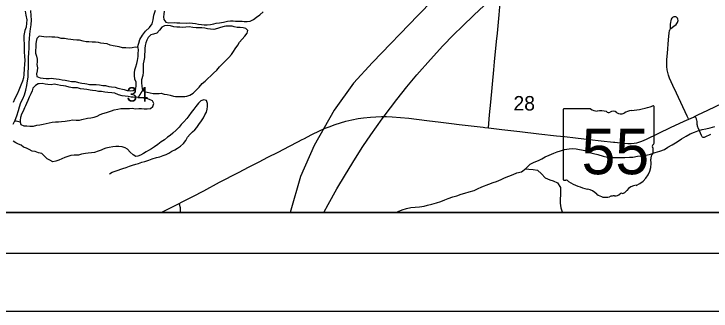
# Model space of a CAD drawing. Extents: x 0 to 1067, y 0 to 440.
# Drawn here: x 227.4 to 348.6, y 0 to 51.6 of the extents above; entities that cross this region are included whole.
import ezdxf

# ---------------------------------------------------------------- set-up
doc = ezdxf.new("R2010")
doc.units = 0
for name, color, linetype in [('GM_X_City_Street', 7, 'Continuous'), ('GM_X_County_Road', 7, 'Continuous'), ('GM_X_Major_River', 7, 'Continuous'), ('GM_X_Minor_Lake', 7, 'Continuous'), ('GM_X_Minor_River', 7, 'Continuous'), ('GM_X_Rail_Line', 7, 'Continuous'), ('GM_X_Section_Text', 7, 'Continuous'), ('GM_X_State_Location', 7, 'Continuous'), ('GM_X_State_Route', 7, 'Continuous'), ('GM_X_State_Shield', 7, 'Continuous'), ('GM_X_Township_Road', 7, 'Continuous'), ('SH_Border', 7, 'Continuous'), ('SH_Cut_Line', 7, 'Continuous'), ('SH_Text', 7, 'Continuous')]:
    doc.layers.add(name, color=color, linetype=linetype)

msp = doc.modelspace()

# ---------------------------------------------------------------- linework, layer by layer
at = {"layer": 'GM_X_City_Street'}
for points in [[(344.76, 33.32), (344.72, 33.41), (344.5, 33.86), (342.65, 37.82), (341.99, 39.2), (341.42, 40.46), (341.23, 40.95), (341.1, 41.42), (341.01, 41.9), (340.94, 42.46), (340.92, 43.03), (340.94, 43.66), (341.04, 44.78), (341.26, 47.12), (341.37, 48.32), (341.41, 48.64), (341.46, 48.84), (341.52, 48.98), (341.64, 49.09), (342.18, 49.48), (342.55, 49.77), (342.7, 49.94), (342.79, 50.1), (342.85, 50.26), (342.89, 50.48), (342.88, 50.68), (342.83, 50.85), (342.76, 50.95), (342.65, 51.03), (342.5, 51.08), (342.35, 51.1), (342.18, 51.09), (342.05, 51.05), (341.94, 50.98), (341.82, 50.85), (341.71, 50.67), (341.62, 50.43), (341.57, 50.19), (341.52, 49.75), (341.51, 49.41), (341.5, 49.02)], [(348.56, 30.65), (347.56, 30.18), (347.46, 30.15), (347.35, 30.14), (347.25, 30.16), (347.15, 30.2), (347.07, 30.28), (347.01, 30.36), (346.95, 30.47), (346.37, 31.81), (346.32, 31.95), (346.29, 32.1), (346.26, 32.24), (346.24, 32.39), (346.22, 32.6), (346.2, 32.91), (346.17, 33.13), (346.13, 33.26), (346.09, 33.38), (346.04, 33.5), (345.89, 33.85)]]:
    msp.add_lwpolyline(points, dxfattribs=at)
at = {"layer": 'GM_X_County_Road'}
msp.add_lwpolyline([(309.92, 31.81), (310.12, 34.06), (310.32, 36.28), (310.87, 41.91), (311, 43.28), (311.35, 46.83), (311.48, 48.24), (311.79, 51.47), (311.99, 53.51), (312.23, 55.99), (312.6, 59.78), (312.83, 62.08)], dxfattribs=at)
at = {"layer": 'GM_X_Major_River'}
for points in [[(227.27, 32.46), (227.63, 33.16), (227.94, 33.93), (228.23, 34.84), (228.4, 35.45), (228.62, 36.23), (228.97, 36.88), (229.24, 37.56), (229.48, 38.36), (229.66, 39.18), (229.76, 39.97), (229.87, 40.63), (229.9, 41.45), (229.94, 42.32), (229.97, 44.05), (230.01, 44.78), (230.05, 45.7), (230.04, 46.63), (230.1, 47.25), (230.18, 48.09), (230.29, 49.02), (230.4, 49.71), (230.44, 50.55), (230.4, 51.28), (230.33, 52.2)], [(229.34, 52.08), (229.49, 51.39), (229.64, 50.59), (229.62, 49.97), (229.54, 49.33), (229.33, 48.72), (229.13, 47.84), (229.14, 47.13), (229.17, 46.4), (229.2, 45.69), (229.19, 44.96), (229.25, 44.25), (229.28, 43.52), (229.24, 42.88), (229.21, 42.08), (229.14, 41.1), (229.06, 40.51), (228.87, 39.9), (228.63, 39.24), (228.27, 38.36), (227.96, 37.68), (227.58, 36.91), (227.29, 36.23)]]:
    msp.add_lwpolyline(points, dxfattribs=at)
at = {"layer": 'GM_X_Minor_Lake'}
for points in [[(253.55, 52.09), (253.47, 51.55), (253.44, 51.07), (253.5, 50.61), (253.84, 50.15), (254.32, 50.08), (255.37, 50.11), (255.75, 50.08), (256.28, 50.03), (257.5, 50.01), (258.01, 50.03), (258.48, 50.02), (258.96, 49.95), (259.48, 49.83), (260.03, 49.75), (260.51, 49.72), (261.01, 49.72), (261.62, 49.78), (262.17, 49.91), (262.58, 49.99), (263.15, 50.08), (263.84, 50.16), (264.52, 50.33), (265.07, 50.42), (265.55, 50.39), (265.94, 50.36), (266.55, 50.37), (267.1, 50.32), (267.44, 50.29), (267.96, 50.29), (268.47, 50.37), (269.08, 50.66), (269.59, 51.04), (270.17, 51.44), (270.74, 51.94)], [(264.25, 43.53), (264.8, 44.02), (265.22, 44.56), (265.59, 45.06), (265.87, 45.55), (266.33, 46.16), (266.64, 46.68), (267.12, 47.2), (267.56, 47.74), (267.96, 48.26), (268.1, 48.74), (267.76, 49.08), (267.29, 49.2), (266.76, 49.25), (266.2, 49.26), (265.72, 49.38), (265.33, 49.46), (264.28, 49.47), (263.94, 49.43), (263.35, 49.23), (262.8, 49.06), (262.18, 48.88), (261.59, 48.94), (261.07, 49.01), (260.59, 49.15), (260.09, 49.18), (259.57, 49.21), (259.07, 49.2), (258.5, 49.25), (257.86, 49.35), (257.29, 49.29), (256.79, 49.27), (256.24, 49.33), (255.74, 49.33), (255.24, 49.38), (254.65, 49.51), (254.15, 49.58), (253.6, 49.56), (253.12, 49.28), (252.7, 48.78), (252.24, 48.28), (251.69, 48.11), (251.19, 47.96), (250.75, 47.53), (250.52, 47.05), (250.35, 46.6), (250.23, 46.12), (250.2, 45.62), (250.19, 45.08), (250.14, 44.58), (250.09, 44.01), (249.99, 43.48), (249.91, 42.94), (249.86, 42.44), (249.88, 41.91), (249.89, 41.46), (249.84, 40.93), (249.62, 40.14)], [(231.8, 47.73), (231.41, 47.31), (231.27, 46.83), (231.22, 46.38), (231.21, 45.81), (231.18, 45.26), (231.17, 44.76), (231.32, 44.26), (231.43, 43.73), (231.47, 43.27), (231.39, 42.8), (231.48, 42.25), (231.47, 41.72), (231.35, 41.22), (231.37, 40.72), (231.98, 40.49), (232.5, 40.46), (233.02, 40.4), (233.55, 40.4), (233.89, 40.42), (234.28, 40.36), (234.75, 40.34), (235.3, 40.26), (235.8, 40.16), (236.3, 40.09), (236.87, 39.97), (237.41, 39.87), (238.05, 39.84), (238.64, 39.71), (239.21, 39.59), (239.71, 39.5), (240.07, 39.44), (240.55, 39.35), (241.16, 39.32), (241.71, 39.33), (242.26, 39.3), (242.85, 39.2), (243.32, 39.15), (243.94, 39.01), (244.37, 38.95), (245.01, 38.86), (245.48, 38.71), (246.57, 38.47), (247.09, 38.33), (247.62, 38.25), (248.14, 38.31), (248.44, 38.52)], [(248.44, 38.52), (248.6, 38.63), (248.68, 39.13), (248.66, 39.74), (248.46, 40.29), (248.36, 40.88), (248.37, 41.39), (248.42, 41.89), (248.63, 42.43), (248.78, 43), (248.87, 43.52), (249.02, 44.18), (249.03, 44.75), (249.06, 45.3), (249.02, 45.77), (248.5, 45.83), (247.99, 45.74), (247.47, 45.68), (246.85, 45.69), (246.31, 45.72), (245.72, 45.89), (244.67, 46.04), (244.13, 46.18), (243.61, 46.39), (243.06, 46.47), (242.54, 46.54), (242.13, 46.64), (241.58, 46.72), (240.99, 46.72), (240.45, 46.75), (239.99, 46.76), (239.47, 46.86), (238.81, 47.03), (238.33, 47.06), (237.69, 47.11), (237.33, 47.18), (236.79, 47.24), (236.22, 47.31), (235.63, 47.34), (235.08, 47.49), (234.53, 47.54), (233.97, 47.59), (233.56, 47.6), (233.01, 47.56), (231.8, 47.73)], [(249.62, 40.14), (249.59, 39.62), (249.65, 39.07), (249.72, 38.57), (250.07, 38.15), (250.55, 38.01), (251.12, 37.89), (251.64, 37.81), (252.19, 37.78), (252.67, 37.8), (253.01, 37.82), (253.53, 37.69), (254.03, 37.6), (254.58, 37.48), (255.17, 37.31), (255.51, 37.26), (256.05, 37.25), (256.64, 37.27), (257.1, 37.28), (257.47, 37.32), (257.99, 37.52), (258.57, 37.86), (259.1, 38.35), (259.61, 38.91), (260.14, 39.52), (260.65, 39.95), (261.13, 40.37), (261.64, 40.87), (262.12, 41.3), (262.68, 41.84), (263.16, 42.4), (263.69, 42.94), (264.25, 43.53)], [(231.62, 39.49), (231.14, 39.18), (230.7, 38.73), (230.56, 38.27), (230.32, 37.73), (230.06, 37.16), (229.8, 36.57), (229.59, 36.03), (229.4, 35.64), (229.24, 35.28), (229, 34.72), (228.72, 34.2), (228.56, 33.63), (228.48, 33.17), (228.5, 32.83), (228.61, 32.37), (229.13, 32.14), (229.67, 32.15), (230.2, 32.08), (230.81, 32.12), (231.38, 32.27), (231.89, 32.35), (232.48, 32.46), (233.03, 32.59), (233.53, 32.67), (234.06, 32.78), (234.63, 32.86), (235.13, 32.88), (235.68, 32.92), (236.29, 32.98), (236.68, 33.02), (237.07, 33.08), (237.59, 33.19), (238.25, 33.16), (238.82, 33.17), (239.19, 33.26), (240.19, 33.47), (240.76, 33.58), (241.36, 33.69), (241.91, 33.84), (242.39, 34.13), (242.89, 34.3), (243.53, 34.48), (244.01, 34.63), (244.36, 34.76), (244.86, 34.96), (245.45, 35.07), (245.98, 35.15), (246.43, 35.15), (247.03, 35.18), (247.53, 35.2), (247.98, 35.22), (248.53, 35.14), (249.15, 35.16)], [(249.15, 35.16), (249.58, 35.15), (250.08, 35.1), (250.6, 35.11), (251.15, 35.15), (251.54, 35.53), (251.75, 36.03), (251.49, 36.49), (250.99, 36.73), (250.51, 36.89), (250.15, 36.94), (249.63, 37.02), (249.13, 37.11), (248.12, 37.13), (247.78, 37.16), (247.26, 37.28), (246.76, 37.31), (246.21, 37.36), (245.58, 37.57), (244.95, 37.83), (244.42, 37.88), (243.74, 37.94), (243.19, 38.04), (242.65, 38.11), (242.1, 38.12), (241.63, 38.22), (241.06, 38.29), (240.67, 38.37), (240.1, 38.46), (239.56, 38.52), (238.99, 38.62), (238.49, 38.74), (237.97, 38.79), (237.58, 38.77), (237.03, 38.89), (236.42, 39.08), (236.04, 39.13), (235.51, 39.16), (234.97, 39.26), (234.4, 39.38), (233.9, 39.3), (233.33, 39.33), (232.83, 39.4), (232.31, 39.53), (231.78, 39.49), (231.62, 39.49)], [(257.29, 29.6), (257.59, 30.17), (258.06, 30.73), (258.47, 31.11), (258.84, 31.47), (259.24, 31.88), (259.58, 32.4), (260.03, 33.05), (260.4, 33.53), (260.63, 34.07), (260.87, 34.54), (261.03, 35.04), (261.09, 35.54), (261.07, 36.05), (260.92, 36.55), (260.42, 36.67), (259.91, 36.49), (259.52, 36.09), (259.06, 35.55), (258.69, 35.07), (258.25, 34.47), (257.81, 33.92), (257.48, 33.45), (256.97, 32.86), (256.51, 32.37), (256.12, 31.94), (255.63, 31.42), (255.05, 30.91), (254.55, 30.5), (254.11, 30.19), (253.58, 29.76), (253.03, 29.36), (252.45, 28.94), (251.88, 28.53), (251.33, 28.18), (250.8, 27.89), (250.38, 27.66), (249.92, 27.35), (249.44, 27.06), (248.96, 26.89), (248.62, 26.82), (248.12, 27.12), (247.63, 27.61), (247.18, 28.09), (246.73, 28.37), (246.21, 28.54), (245.66, 28.55), (245.11, 28.6), (244.59, 28.54), (243.97, 28.41), (243.4, 28.3), (242.92, 28.11), (242.55, 27.95), (242.03, 27.78), (241.39, 27.56), (240.88, 27.45), (240.34, 27.41), (239.86, 27.37), (239.13, 27.22), (238.62, 27.09), (237.89, 27.06), (237.32, 27.04), (236.8, 26.84), (236.25, 26.67), (235.74, 26.45), (235.2, 26.23), (234.69, 26.03), (234.17, 25.94), (233.67, 26.18), (233.17, 26.43), (232.74, 26.9), (232.27, 27.38), (231.7, 27.46), (231.09, 27.69), (230.55, 27.77), (230.05, 28.07), (229.57, 28.26), (229.05, 28.49), (228.67, 28.8), (228.22, 29.01), (227.72, 29.24), (227.27, 29.48)], [(244.02, 23.81), (244.48, 24.1), (245.03, 24.29), (245.51, 24.47), (246.01, 24.62), (246.36, 24.76), (246.91, 24.95), (247.53, 25.17), (248.03, 25.35), (248.6, 25.52), (249.06, 25.63), (249.63, 25.85), (250.18, 25.98), (250.84, 26.2), (251.42, 26.42), (252.22, 26.64), (252.79, 26.79), (253.34, 26.99), (253.91, 27.19), (254.34, 27.41), (254.87, 27.76), (255.38, 28.01), (255.86, 28.28), (256.37, 28.63), (256.87, 29.08), (257.29, 29.6)]]:
    msp.add_lwpolyline(points, dxfattribs=at)
at = {"layer": 'GM_X_Minor_River'}
for points in [[(248.92, 45.78), (249.14, 46.55), (249.33, 47.16), (249.75, 47.91), (250.29, 48.61), (251, 49.26), (251.47, 49.87), (251.61, 50.59), (251.74, 51.41), (252.05, 52.23)], [(227.55, 33.01), (227.82, 33.05), (228.5, 32.85)], [(309.98, 22.06), (310.74, 22.32), (311.31, 22.51), (312.11, 22.86), (312.73, 23.13), (313.47, 23.41), (314.2, 23.74), (314.84, 23.98), (315.67, 24.19), (316.45, 24.77), (317.17, 25.51), (317.88, 25.86), (318.62, 26.17), (319.19, 26.43), (319.77, 26.79), (320.48, 27.05), (321.3, 27.42), (321.88, 27.64), (322.45, 27.84), (323.18, 28.05), (323.98, 28.2), (324.58, 28.24), (325.17, 28.16), (326.67, 27.9), (327.5, 27.55), (328.18, 27.35), (328.95, 27.16), (329.86, 26.89), (330.61, 26.74), (331.52, 26.64), (332.25, 26.65), (332.84, 26.66), (333.66, 26.67), (334.43, 26.72), (335.05, 26.74), (335.83, 26.88), (336.62, 26.98), (337.35, 27.08), (338.13, 27.25), (338.89, 27.54), (339.73, 27.75), (340.54, 28.08), (341.14, 28.46), (341.87, 28.85), (342.75, 29.39), (343.51, 29.9), (344.29, 30.36), (344.98, 30.76), (345.74, 31.07), (346.31, 31.28), (347.09, 31.54), (347.73, 31.65), (348.46, 31.8), (349.31, 32.03)], [(316.34, 24.69), (316.95, 24.65), (317.68, 24.59), (318.45, 24.49), (319.17, 23.84), (319.77, 23.14), (320.59, 22.79), (321.17, 22.64), (321.94, 22.29), (322.43, 21.48), (322.46, 20.82), (322.43, 20.09), (322.4, 19.52), (322.4, 18.72), (322.5, 17.95), (322.72, 17.24), (322.78, 17.11)], [(293.91, 17.11), (294.23, 17.26), (294.94, 17.59), (295.7, 17.79), (296.45, 17.96), (297.18, 18.03), (297.91, 18.09), (298.76, 18.21), (299.35, 18.36), (300.1, 18.55), (300.88, 18.79), (301.64, 19.03), (302.35, 19.34), (302.95, 19.53), (303.75, 19.81), (304.41, 20.03), (305.21, 20.31), (305.83, 20.49), (306.57, 20.72), (307.44, 20.96), (308.03, 21.22), (308.79, 21.58), (309.98, 22.06)]]:
    msp.add_lwpolyline(points, dxfattribs=at)
at = {"layer": 'GM_X_Rail_Line'}
for points in [[(330.43, 84.61), (324.5, 78.63), (310.59, 64.57), (297.7, 51.37), (289.79, 43.17), (286.47, 39.55), (283.11, 34.86), (279.61, 28.76), (277.25, 23.39), (275.45, 17.11)], [(281.31, 17.11), (282.06, 18.52), (283.58, 21.24), (285.05, 23.74), (286.82, 26.55), (288.11, 28.57), (289.49, 30.6), (291.47, 33.38), (292.88, 35.27), (294.01, 36.75), (295.75, 38.93), (297.48, 41.04), (299.85, 43.69), (302.01, 46.04), (303.85, 47.95), (305.4, 49.48), (307.36, 51.37), (309.16, 53.05)]]:
    msp.add_lwpolyline(points, dxfattribs=at)
at = {"layer": 'GM_X_State_Route'}
for points in [[(331.89, 29.32), (333.27, 29.17), (334.15, 29.1), (334.75, 29.1), (335.27, 29.14), (335.72, 29.22), (336.09, 29.31), (336.61, 29.51), (337.4, 29.86), (341.58, 31.85), (343.95, 32.95), (344.76, 33.32), (345.56, 33.7), (345.89, 33.85), (346.35, 34.07), (348.08, 34.9), (350.64, 36.11), (351.62, 36.57)], [(280.69, 31.37), (281.43, 31.7), (281.68, 31.81), (282.2, 32.02), (283.28, 32.42), (284.17, 32.71), (285.14, 32.97), (286.15, 33.22), (287.25, 33.43), (288.21, 33.57), (289.39, 33.69), (290.34, 33.75), (291.32, 33.78)], [(291.32, 33.78), (291.54, 33.78), (292.2, 33.78)], [(292.2, 33.78), (293.21, 33.74), (294.61, 33.64), (296.09, 33.47), (299.23, 33.07), (301.64, 32.79), (303.49, 32.57)], [(303.49, 32.57), (304.86, 32.42), (309, 31.92), (309.31, 31.88)], [(309.31, 31.88), (309.92, 31.81), (312.26, 31.54), (315.37, 31.17), (318.7, 30.8), (321.75, 30.45)], [(277.8, 29.92), (279.23, 30.65), (280.52, 31.3), (280.69, 31.37)], [(321.75, 30.45), (323.18, 30.29), (325.07, 30.07), (327.48, 29.81), (329.53, 29.57), (331.65, 29.35), (331.89, 29.32)], [(253.01, 17.11), (254.51, 17.87), (256.15, 18.68), (256.67, 18.95), (258.52, 19.91), (260.41, 20.9), (263.17, 22.36), (266.46, 24.04), (268.34, 25.03), (270.03, 25.9), (271.58, 26.71), (273.34, 27.6), (275.35, 28.66), (276.79, 29.4)], [(276.79, 29.4), (277.54, 29.79), (277.8, 29.92)]]:
    msp.add_lwpolyline(points, dxfattribs=at)
at = {"layer": 'GM_X_State_Shield'}
for p, q in [((338.73, 29.14), (338.73, 35.42)), ((322.91, 34.92), (322.91, 22.91)), ((327.7, 35.13), (323.06, 35.13)), ((338.73, 29.14), (338.73, 29.14))]:
    msp.add_line(p, q, dxfattribs=at)
for centre, radius, start, end in [((333.09, 51.5), 16.78, 275.8445, 288.9065), ((338.55, 35.45), 0.176, 351.8621, 97.738), ((323.09, 34.94), 0.183, 98.1301, 188.1301), ((328.8, 36.52), 1.78, 231.6195, 271.1119), ((329.39, 28.38), 6.38, 80.4867, 94.9883), ((330.84, 35.01), 0.513, 219.7921, 297.1024), ((331.59, 33.62), 1.07, 54.4667, 119.1411), ((332.97, 35.52), 1.28, 233.8562, 294.8282), ((335.23, 31.46), 3.38, 97.3462, 120.7689), ((338.54, 29.12), 0.188, 289.6038, 7.7341), ((338.69, 28.68), 0.273, 107.944, 210.337), ((336.95, 27.89), 1.64, 340.033, 23.6496), ((339.36, 26.51), 1.19, 136.8065, 186.9296), ((334.03, 25.71), 4.2, 292.3089, 8.9858), ((323.09, 22.89), 0.185, 171.9584, 258.3066), ((323.12, 24.11), 1.41, 267.339, 280.6039), ((323.41, 22.22), 0.509, 29.7484, 93.2717), ((329.83, 33.01), 12.12, 240.4129, 257.1985), ((335.8, 19.54), 2.3, 94.4031, 142.5768), ((326.22, 17.52), 3.79, 47.1842, 75.836), ((332.89, 21.75), 1.36, 282.8732, 323.2771), ((330.32, 22.16), 2.41, 230.7004, 286.2918), ((331.71, 18.01), 1.98, 85.6951, 111.2099), ((331.89, 21.26), 1.28, 268.777, 315.5493), ((333.04, 20.1), 0.361, 65.7517, 132.6484)]:
    msp.add_arc(centre, radius, start, end, dxfattribs=at)
at = {"layer": 'GM_X_Township_Road'}
for points in [[(256.36, 17.11), (256.36, 17.19), (256.37, 17.53), (256.36, 17.72), (256.35, 17.91), (256.32, 18.1), (256.24, 18.38), (256.15, 18.68)], [(216.02, 17.11), (539, 17.11)]]:
    msp.add_lwpolyline(points, dxfattribs=at)
at = {"layer": 'SH_Border'}
msp.add_lwpolyline([(30, 430), (670, 430), (670, 10), (30, 10)], close=True, dxfattribs=at)
at = {"layer": 'SH_Cut_Line'}
msp.add_lwpolyline([(0, 0), (680, 0), (680, 440), (0, 440)], close=True, dxfattribs=at)
at = {"layer": 'SH_Text'}
msp.add_lwpolyline([(131, 425.11), (539, 425.11), (539, 17.11), (131, 17.11)], close=True, dxfattribs=at)

# ---------------------------------------------------------------- texts
at = {"layer": 'GM_X_Section_Text'}
for s, p in [('34', (247, 36.38)), ('28', (314.28, 34.83))]:
    msp.add_text(s, height=2.511, rotation=0, dxfattribs=at).set_placement(p)
at = {"layer": 'GM_X_State_Location'}
for s in ['s', 'r']:
    msp.add_text(s, height=0.0114, dxfattribs=at).set_placement((330.64, 28.12))
msp.add_text('55', height=0.0114, rotation=0, dxfattribs=at).set_placement((327.78, 27.29))
at = {"layer": 'GM_X_State_Shield'}
msp.add_text('55', height=7.91, dxfattribs=at).set_placement((326.11, 23.76))

doc.saveas('drawing.dxf')
